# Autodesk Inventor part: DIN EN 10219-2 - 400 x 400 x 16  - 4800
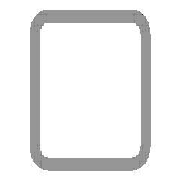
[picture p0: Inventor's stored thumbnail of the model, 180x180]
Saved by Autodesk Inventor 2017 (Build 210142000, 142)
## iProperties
IsCustomPart: 1
Created: 2017-11
Part Number: DIN EN 10219-2 - 400 x 400 x 16  - 4800
Material: Steel, Mild
Description: Cold formed welded structural hollow sections of non-alloy and fine grain structural steel
Document SubType Name: Modeling
Standard: DIN
Designer: iusti
Standard Revision: 2006-07
Standards Organization: DIN
Language: en-US
Size Designation: 400 x 400 x 16
Categories: <MemberInstance><Categories><Category DisplayName="Structural Shapes" InternalName="089c4875-fa83-4c05-b084-43b9cc11f5ed" Mnemonic="GRDR"><CategoryParameter Dis
Stock Number: 400 x 400 x 16
Density: 7.85 g/cm^3
Appearance: Semi-Polished
Mass: 884622 g
Surface Area: 141333 cm^2
Volume: 112691 cm^3
_CCFamilyMember: 142
_CCFamilyDisplayName: DIN EN 10219-2 (Square Hollow Section - Cold Formed) - Cold formed welded structural hollow sections of non-alloy and fine grain structural steel
_FrameMemberDoc: Frame Member File
_Version: 15.0.0
_GetPNFromCC: 1
G_L: 4800.000 mm
G_W: 400.000 mm
G_H: 400.000 mm
+6FBBBA41-A689-4153-B866-6340EAF31301+CUTDETAIL1: Cut
Author: iusti
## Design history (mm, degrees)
node "Start plane"
node "End plane"
sketch "Sketch"
  geometry: L1 (-200, -152)-(-200, 152); L2 (-152, 200)-(152, 200); L3 (200, 152)-(200, -152); L4 (152, -200)-(-152, -200); L5 (-152, 184)-(152, 184); L6 (184, 152)-(184, -152); L7 (152, -184)-(-152, -184); L8 (-184, -152)-(-184, 152); L9 (0, 293.918)-(0, -293.918) reference; L10 (-293.918, 0)-(293.918, 0) reference; A1 r 48 centre (-152, -152) between (-200, -152) and (-152, -200); A2 r 48 centre (-152, 152) between (-152, 200) and (-200, 152); A3 r 48 centre (152, 152) between (200, 152) and (152, 200); A4 r 48 centre (152, -152) between (152, -200) and (200, -152); A5 r 32 centre (-152, 152) between (-152, 184) and (-184, 152); A6 r 32 centre (152, 152) between (184, 152) and (152, 184); A7 r 32 centre (152, -152) between (152, -184) and (184, -152); A8 r 32 centre (-152, -152) between (-184, -152) and (-152, -184)
  constraints: 16 end point, 16 point on circle, 8 centre point, 8 tangent, 4 parallel, 3 equal radius, 2 perpendicular, 7 other
  dimensions: "d7" = 48 radius of A1 (= G_IR); "d10" = 400 distance between parallel lines of L2 L4 (= G_H); "d11" = 400 distance between parallel lines of L1 L3 (= G_W); "d12" = 16 distance between parallel lines of L3 L6 (= G_T); "d15" = 200 distance between parallel lines of L2 L10 (= 0.5 x d10); "d16" = 200 distance between parallel lines of L9 L3 (= 0.5 x d11)
extrude "Body" new body sketch "Sketch" stored distance "d3" = 4800 (= G_L); taper "d4" = 0 deg
node "Driven Length"
  sketch "Sketch3"
    geometry: L1 (0, 0)-(10, 0) reference
    constraints: 2 end point, 1 horizontal
  workplane "Work Plane3"
  sketch "Sketch4"
    geometry: L1 (-2, 0)-(12, 0) reference; L2 (-2, 4800)-(12, 4800) reference
    dimensions: "d18" = 4800 distance between parallel lines of L1 L2 (derived)
workplane "Work Plane4"
split "Split1"
body "Solid1"
other parameters: "G_W" = 400 [user parameter; used in 1 equation term], "G_H" = 400 [user parameter; used in 1 equation term], "G_T" = 16 [user parameter; used in 1 equation term], "G_IR" = 48 [user parameter; used in 1 equation term], "G_L" = 4800 (= d18) [user parameter; used in 1 equation term], "G_OFFSET_START" = 0 [user parameter; used in 1 equation term], "d13" = 0 (computed from G_OFFSET_START), "d17" = 90 deg
